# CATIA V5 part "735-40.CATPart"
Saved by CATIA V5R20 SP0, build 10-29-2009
Part number: 735-40
Bounding box of the stored display mesh (mm): x -33 to 33, y -32.999 to 32.999, z -37 to 45
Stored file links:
  C:\Users\Utente\Desktop\IO LAVORO\3D X SITO CF\X SITO\735\735-40.CATPart
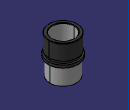
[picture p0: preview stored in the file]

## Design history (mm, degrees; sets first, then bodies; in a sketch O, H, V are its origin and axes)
Set1
  DatumSurface1 to DatumSurface25 "735-40"
Body1 (main body)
